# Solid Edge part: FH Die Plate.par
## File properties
Author: davee
Template: Normal.par
Last saved by: davee
Revision: 14
Application: Solid Edge
Accuracy: 0.990
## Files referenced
..\Loose Support Mould.asm
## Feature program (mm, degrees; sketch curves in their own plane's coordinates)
sketch for "unnamed Protrusion 1" plane through (0, 0, 0) normal (0, 0, 1) x-axis (1, 0, 0)
  line (-100, -100) -> (100, -100)
  line (100, -100) -> (100, 100)
  line (100, 100) -> (-100, 100)
  line (-100, 100) -> (-100, -100)
  dimension (linear) = 100
  dimension (linear) = 100
extrude "unnamed Protrusion 1" add finite 35.22 along -normal
sketch for "Hole_1" plane through (0, 0, 0) normal (0, 0, 1) x-axis (1, 0, 0)
hole "Hole_1" diameter 6 through
sketch for "Hole_2" plane through (0, 0, -35.22) normal (0, 0, -1) x-axis (-1, 0, 0)
  hole centre (-80, -49) bore radius 5.053
hole "Hole_2" finite  VBottomAngle = 118 deg; ThreadDepth = 2 mm
sketch for "unnamed Hole 1" plane through (0, 0, -35.22) normal (0, 0, -1) x-axis (-1, 0, 0)
  hole centre (80, -49) bore radius 5.053
hole "unnamed Hole 1" finite
sketch for "unnamed Hole 2" plane through (0, 0, -35.22) normal (0, 0, -1) x-axis (-1, 0, 0)
  hole centre (80, 49) bore radius 5.053
hole "unnamed Hole 2" finite
sketch for "unnamed Hole 3" plane through (0, 0, -35.22) normal (0, 0, -1) x-axis (-1, 0, 0)
  hole centre (-80, 49) bore radius 5.053
hole "unnamed Hole 3" finite
pattern "unnamed Pattern 1" of "Hole_2", "unnamed Hole 1", "unnamed Hole 2", "unnamed Hole 3"
sketch for "ExtrudedCutout_1" #1 plane through (0, 0, -35.22) normal (0, 0, -1) x-axis (-1, 0, 0)
  circle centre (77, 77) radius 16
sketch for "ExtrudedCutout_1" #2 plane through (0, 0, -35.22) normal (0, 0, -1) x-axis (-1, 0, 0)
  circle centre (77, -77) radius 16
sketch for "ExtrudedCutout_1" #3 plane through (0, 0, -35.22) normal (0, 0, -1) x-axis (-1, 0, 0)
  circle centre (-77, -77) radius 16
sketch for "ExtrudedCutout_1" #4 plane through (0, 0, -35.22) normal (0, 0, -1) x-axis (-1, 0, 0)
  circle centre (-77, 77) radius 16
extrude "ExtrudedCutout_1" cut finite 6 along -normal
sketch for "unnamed Cutout 1" #1 plane through (0, 0, -35.22) normal (0, 0, -1) x-axis (-1, 0, 0)
  circle centre (77, 77) radius 13.5
sketch for "unnamed Cutout 1" #2 plane through (0, 0, -35.22) normal (0, 0, -1) x-axis (-1, 0, 0)
  circle centre (77, -77) radius 13.5
sketch for "unnamed Cutout 1" #3 plane through (0, 0, -35.22) normal (0, 0, -1) x-axis (-1, 0, 0)
  circle centre (-77, -77) radius 13.5
sketch for "unnamed Cutout 1" #4 plane through (0, 0, -35.22) normal (0, 0, -1) x-axis (-1, 0, 0)
  circle centre (-77, 77) radius 13.5
extrude "unnamed Cutout 1" cut through along -normal
boolean "unnamed Boolean 1"
delete faces "unnamed DeleteFaces 1"
boolean "unnamed Boolean 2"
sketch for "Hole_6" plane through (0, 100, -17.61) normal (0, 1, 0) x-axis (1, 0, 0)
hole "Hole_6" finite  VBottomAngle = 118 deg; ThreadDepth = 2 mm
sketch for "unnamed Hole 4" plane through (0, 100, -17.61) normal (0, 1, 0) x-axis (1, 0, 0)
hole "unnamed Hole 4" finite
pattern "unnamed Pattern 2" of "Hole_6", "unnamed Hole 4"
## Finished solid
Body 1: solid body, 89 faces, 205 edges, 116 vertices.
  Faces by surface: plane 43, cylinder 32, sphere 6, torus 4, blend 2, cone 2
  Edges by curve: line 136, circle 59, ellipse 10
Body 2: solid body, 26 faces, 56 edges, 32 vertices.
  Faces by surface: cylinder 12, torus 8, plane 6
  Edges by curve: circle 32, line 24
Body 3: solid body, 64 faces, 123 edges, 58 vertices.
  Faces by surface: cylinder 31, plane 15, torus 8, cone 6, blend 2, sphere 2
  Edges by curve: circle 74, line 45, ellipse 4
Bounding box of the edges (mm; curved faces can reach further): 200.000 x 200.000 x 58.057, from (-100, -100, -35.22) to (100, 100, 22.8375).
Cylindrical faces by radius (mm): R0.7575 x4, R0.812 x6, R1.01 x8, R1.1165 x2, R1.515 x2, R1.6747 x2, R2.03 x26, R2.233 x2, R3 x1, R3.03 x2, R3.045 x4, R4.188 x2, R5.053 x4, R10.15 x1, R13.5 x4, R16 x4, R25.8825 x1
Conical faces (half-angle, radius in mm at the cone's reference point): 59 deg R2.233 x2, 59 deg R4.188 x2, 59 deg R5.053 x4
Toroidal faces (ring radius, tube radius in mm): R0.505 r1.01 x4, R0.7575 r0.7575 x2, R2.02 r1.01 x4, R2.233 r0.812 x4, R2.2725 r0.7575 x2, R4.06 r2.03 x4
Spherical faces by radius (mm): R2.03 x8
Planar faces by outward normal: +x 8, +y 11, +z 15, -x 8, -y 7, -z 9, oblique 6
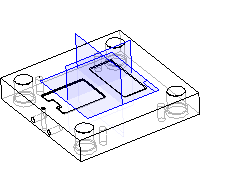
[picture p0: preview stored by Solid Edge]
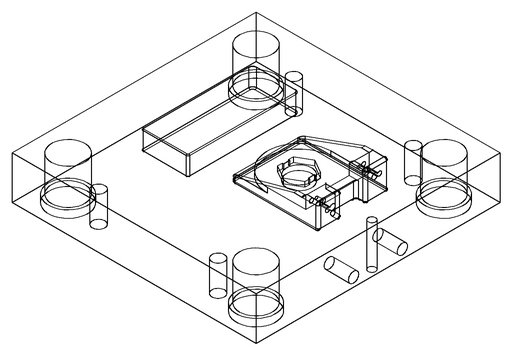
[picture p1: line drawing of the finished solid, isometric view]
